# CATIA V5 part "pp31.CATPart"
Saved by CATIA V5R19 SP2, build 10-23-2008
Part number: pp31
Bounding box of the stored display mesh (mm): x 10 to 15, y -422.25 to -244.868, z -52.25 to 37.903
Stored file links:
  C:\Users\Welcome\Documents\thinkm2\pp31.CATPart
  C:\Users\Welcome\Documents\thinkm2\Brasmeca.CATProduct
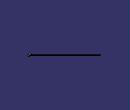
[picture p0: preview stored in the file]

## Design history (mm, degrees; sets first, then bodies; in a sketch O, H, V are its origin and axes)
AxisSystem1: origin (0, 0, 0), X (1, 0, 0), Y (0, 1, 0), Z (0, 0, 1)
Set1
  Plane1: linked copy from another document
  Line1: linked copy from another document
  Plane2: linked copy from another document
  Sketch1, origin (5, 0, 0), H (0, 1, 0), V (0, 0, 1), geometry linked from another document
Body1 (main body)
  Sketch2 on Plane1, origin (15, 0, 0), H (0, 1, 0), V (0, 0, 1)
    circle A1 centre (-420, -50) radius 2.25
    reference projected point E1 (-420, -50) from Line1
    radius A1 = 2.25
    distance A1 E1 = 2.25
  Pad1: profile Sketch2, direction (-1, 0, 0), length 5
  Sketch3 on Plane2, origin (0, -206, -103), H (1, 0, 0), V (0, -0.4472, 0.8944)
    line L1 (13.2601, 143.5596) -> (14.899, 143.5596)
    line L2 (14.899, 143.5596) -> (14.899, 142.8113)
    line L3 (14.899, 142.8113) -> (13.2601, 142.8113)
    line L4 (13.2601, 142.8113) -> (13.2601, 143.5596)
  Pad2: profile Sketch3, direction (0, -0.8944, -0.4472), length 167
  Pad3: profile Sketch3, direction (0, 0.8944, 0.4472), length 27.95
  Pocket1: profile Sketch1, direction (1, 0, 0), length 27.95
